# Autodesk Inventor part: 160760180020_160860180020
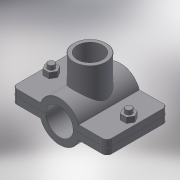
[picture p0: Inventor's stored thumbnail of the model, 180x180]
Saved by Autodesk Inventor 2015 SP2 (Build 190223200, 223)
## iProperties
Created: 2017-05
Part Number: 160760180020_160860180020
Material: Generic
Description: PLASSON SADDLE 180-2"
Document SubType Name: Modeling
Designer: KIM
Density: 1 g/cm^3
Appearance: Default
Author: KIM
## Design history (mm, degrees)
derived "16076.ipt"
feature "Solid1::16076.ipt"
feature "Solid2::16076.ipt"
tag "TaggingFeature1"
body "Solid1"
other parameters: "d0" = 198, "d1" = 245, "d4" = 154, "d5" = 0, "d6" = 12.25, "d7" = 245, "d8" = 0.1, "d10" = 0, "d11" = 1.8, "d14" = 73.6528, "d20" = 1.8, "d23" = 1.8, "d36" = 15, "d37" = 12, "d38" = 98, "d39" = 0, "d40" = 3, "d41" = 5, "d42" = 0, "d44" = 3, "d45" = 0, "d46" = 1.8, "d51" = 133, "d52" = 56.656, "d54" = 0, "d57" = 0, "d58" = 194.4, "d60" = 0, "d62" = 15, "d63" = 12, "G_" = 56.656, "A_" = 133, "L_" = 245, "L_1" = 154
